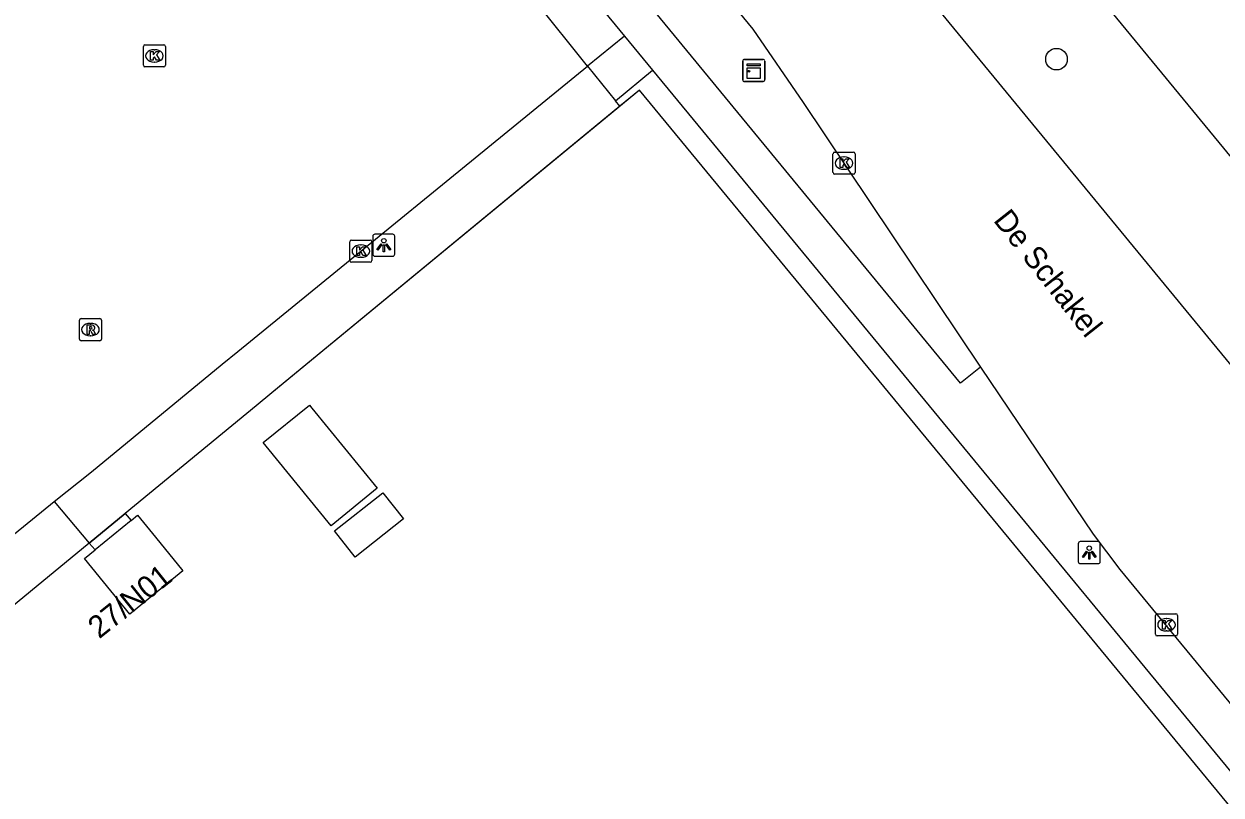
# Model space of a CAD drawing. Extents: x 156141 to 158132, y 385651 to 388399.
# Drawn here: x 157222.2 to 157276.3, y 386292.7 to 386327.6 of the extents above; entities that cross this region are included whole.
import ezdxf

# ---------------------------------------------------------------- set-up
doc = ezdxf.new("R2010")
doc.units = 0
for name, color, linetype in [('IMGEO_Boom', 7, 'Continuous'), ('IMGEO_Groenvoorziening', 7, 'Continuous'), ('IMGEO_Haag', 7, 'Continuous'), ('IMGEO_Hek', 7, 'Continuous'), ('IMGEO_Kast', 7, 'Continuous'), ('IMGEO_Kolk', 7, 'Continuous'), ('IMGEO_Lichtpunt', 7, 'Continuous'), ('IMGEO_Openbare_ruimte_label', 7, 'Continuous'), ('IMGEO_Pand', 7, 'Continuous'), ('IMGEO_Pand_nummerreeks', 7, 'Continuous'), ('IMGEO_Rijbaan_lokaal_gesloten', 7, 'Continuous'), ('IMGEO_Rioolput', 7, 'Continuous'), ('IMGEO_Voetpad_open', 7, 'Continuous')]:
    doc.layers.add(name, color=color, linetype=linetype)

msp = doc.modelspace()

# ---------------------------------------------------------------- linework, layer by layer
at = {"layer": 'IMGEO_Boom'}
msp.add_circle((157268.887, 386325.993), 0.489, dxfattribs=at)
at = {"layer": 'IMGEO_Groenvoorziening'}
for points in [[(157247.676, 386325.673), (157242.926, 386331.607), (157204.09, 386378.741)], [(157318.008, 386237.675), (157310.24, 386250.894), (157308.881, 386253.009), (157305.737, 386257.034), (157297.068, 386267.539), (157250.016, 386324.597), (157249.125, 386323.863)]]:
    msp.add_lwpolyline(points, dxfattribs=at)
at = {"layer": 'IMGEO_Haag'}
msp.add_lwpolyline([(157225.13, 386304.108), (157163.286, 386253.19), (157161.441, 386255.415), (157161.905, 386255.778), (157223.541, 386305.983)], dxfattribs=at)
at = {"layer": 'IMGEO_Hek'}
for points in [[(157297.068, 386267.539), (157250.016, 386324.597), (157233.385, 386310.904)], [(157233.385, 386310.904), (157232.673, 386310.318)], [(157232.673, 386310.318), (157226.757, 386305.447)], [(157226.757, 386305.447), (157225.13, 386304.108)], [(157225.13, 386304.108), (157163.286, 386253.19)]]:
    msp.add_lwpolyline(points, dxfattribs=at)
at = {"layer": 'IMGEO_Kast'}
for p, q in [((157254.691, 386325.06), (157254.691, 386325.901)), ((157254.691, 386325.901), (157254.691, 386325.06)), ((157254.766, 386325.985), (157255.607, 386325.985)), ((157255.607, 386325.985), (157254.766, 386325.985)), ((157255.691, 386325.91), (157255.691, 386325.069)), ((157255.691, 386325.069), (157255.691, 386325.91)), ((157255.616, 386324.985), (157254.775, 386324.985)), ((157254.775, 386324.985), (157255.616, 386324.985))]:
    msp.add_line(p, q, dxfattribs=at)
for points in [[(157254.886, 386325.775), (157255.486, 386325.775), (157255.486, 386325.69), (157254.886, 386325.69), (157254.886, 386325.775)], [(157254.886, 386325.6), (157255.486, 386325.6), (157255.486, 386325.111), (157254.886, 386325.111), (157254.886, 386325.6)]]:
    msp.add_lwpolyline(points, dxfattribs=at)
msp.add_circle((157254.97, 386325.449), 0.0377, dxfattribs=at)
for centre, start, end in [((157254.769, 386325.907), 92.4484, 184.2845), ((157254.769, 386325.907), 92.4484, 184.2845), ((157255.613, 386325.907), 2.4484, 94.2845), ((157255.613, 386325.907), 2.4484, 94.2845), ((157254.769, 386325.063), 182.4484, 274.2845), ((157254.769, 386325.063), 182.4484, 274.2845), ((157255.613, 386325.063), 272.4484, 4.2845), ((157255.613, 386325.063), 272.4484, 4.2845)]:
    msp.add_arc(centre, 0.0779, start, end, dxfattribs=at)
at = {"layer": 'IMGEO_Kolk'}
for p, q in [((157227.574, 386325.716), (157227.574, 386326.568)), ((157227.649, 386326.642), (157228.501, 386326.642)), ((157228.575, 386326.568), (157228.575, 386325.716)), ((157228.062, 386326.422), (157228.087, 386326.422)), ((157228.501, 386325.642), (157227.649, 386325.642)), ((157228.085, 386325.862), (157228.06, 386325.862)), ((157258.775, 386320.865), (157258.775, 386321.717)), ((157258.85, 386321.791), (157259.702, 386321.791)), ((157259.263, 386321.571), (157259.288, 386321.571)), ((157259.776, 386321.717), (157259.776, 386320.865)), ((157259.286, 386321.011), (157259.261, 386321.011)), ((157259.702, 386320.791), (157258.85, 386320.791)), ((157236.99, 386317.81), (157237.842, 386317.81)), ((157236.915, 386316.884), (157236.915, 386317.736)), ((157237.403, 386317.59), (157237.428, 386317.59)), ((157237.916, 386317.736), (157237.916, 386316.884)), ((157237.842, 386316.81), (157236.99, 386316.81)), ((157237.426, 386317.03), (157237.401, 386317.03)), ((157273.365, 386299.983), (157273.365, 386300.835)), ((157273.44, 386300.909), (157274.292, 386300.909)), ((157273.853, 386300.689), (157273.878, 386300.689)), ((157274.366, 386300.835), (157274.366, 386299.983)), ((157274.292, 386299.909), (157273.44, 386299.909)), ((157273.876, 386300.129), (157273.851, 386300.129))]:
    msp.add_line(p, q, dxfattribs=at)
for points in [[(157227.574, 386325.716), (157227.574, 386326.568)], [(157227.649, 386326.642), (157228.501, 386326.642)], [(157228.575, 386326.568), (157228.575, 386325.716)], [(157227.895, 386326.342), (157228.018, 386326.342), (157228.018, 386326.191), (157228.148, 386326.342), (157228.312, 386326.342), (157228.166, 386326.191), (157228.319, 386325.942), (157228.167, 386325.942), (157228.082, 386326.106), (157228.018, 386326.039), (157228.018, 386325.942), (157227.895, 386325.942), (157227.895, 386326.342)], [(157228.501, 386325.642), (157227.649, 386325.642)], [(157258.775, 386320.865), (157258.775, 386321.717)], [(157258.85, 386321.791), (157259.702, 386321.791)], [(157259.776, 386321.717), (157259.776, 386320.865)], [(157259.096, 386321.491), (157259.219, 386321.491), (157259.219, 386321.34), (157259.349, 386321.491), (157259.513, 386321.491), (157259.367, 386321.34), (157259.52, 386321.091), (157259.368, 386321.091), (157259.283, 386321.255), (157259.219, 386321.188), (157259.219, 386321.091), (157259.096, 386321.091), (157259.096, 386321.491)], [(157259.702, 386320.791), (157258.85, 386320.791)], [(157236.99, 386317.81), (157237.842, 386317.81)], [(157236.915, 386316.884), (157236.915, 386317.736)], [(157237.236, 386317.51), (157237.359, 386317.51), (157237.359, 386317.359), (157237.489, 386317.51), (157237.653, 386317.51), (157237.507, 386317.359), (157237.66, 386317.11), (157237.508, 386317.11), (157237.423, 386317.274), (157237.359, 386317.207), (157237.359, 386317.11), (157237.236, 386317.11), (157237.236, 386317.51)], [(157237.916, 386317.736), (157237.916, 386316.884)], [(157237.842, 386316.81), (157236.99, 386316.81)], [(157273.365, 386299.983), (157273.365, 386300.835)], [(157273.44, 386300.909), (157274.292, 386300.909)], [(157273.686, 386300.609), (157273.809, 386300.609), (157273.809, 386300.458), (157273.939, 386300.609), (157274.103, 386300.609), (157273.957, 386300.458), (157274.11, 386300.209), (157273.958, 386300.209), (157273.873, 386300.373), (157273.809, 386300.306), (157273.809, 386300.209), (157273.686, 386300.209), (157273.686, 386300.609)], [(157274.366, 386300.835), (157274.366, 386299.983)], [(157274.292, 386299.909), (157273.44, 386299.909)]]:
    msp.add_lwpolyline(points, dxfattribs=at)
for centre, start, end in [((157227.651, 386326.566), 91.552, 178.448), ((157227.651, 386326.566), 91.552, 178.448), ((157228.499, 386326.566), 1.552, 88.448), ((157228.499, 386326.566), 1.552, 88.448), ((157227.651, 386325.718), 181.552, 268.448), ((157227.651, 386325.718), 181.552, 268.448), ((157228.499, 386325.718), 271.552, 358.448), ((157228.499, 386325.718), 271.552, 358.448), ((157258.852, 386321.715), 91.552, 178.448), ((157258.852, 386321.715), 91.552, 178.448), ((157259.7, 386321.715), 1.552, 88.448), ((157259.7, 386321.715), 1.552, 88.448), ((157258.852, 386320.867), 181.552, 268.448), ((157258.852, 386320.867), 181.552, 268.448), ((157259.7, 386320.867), 271.552, 358.448), ((157259.7, 386320.867), 271.552, 358.448), ((157236.992, 386317.734), 91.552, 178.448), ((157236.992, 386317.734), 91.552, 178.448), ((157237.84, 386317.734), 1.552, 88.448), ((157237.84, 386317.734), 1.552, 88.448), ((157236.992, 386316.886), 181.552, 268.448), ((157236.992, 386316.886), 181.552, 268.448), ((157237.84, 386316.886), 271.552, 358.448), ((157237.84, 386316.886), 271.552, 358.448), ((157273.442, 386300.833), 91.552, 178.448), ((157273.442, 386300.833), 91.552, 178.448), ((157274.29, 386300.833), 1.552, 88.448), ((157274.29, 386300.833), 1.552, 88.448), ((157273.442, 386299.985), 181.552, 268.448), ((157273.442, 386299.985), 181.552, 268.448), ((157274.29, 386299.985), 271.552, 358.448), ((157274.29, 386299.985), 271.552, 358.448)]:
    msp.add_arc(centre, 0.0765, start, end, dxfattribs=at)
for centre, major_axis, ratio, start_param, end_param in [((157228.061, 386326.142), (-0.387, 0.002), 0.722429, 4.712389, 7.853982), ((157228.086, 386326.142), (-0.39, 0.002), 0.717154, 1.570796, 4.712389), ((157259.262, 386321.291), (-0.387, 0.002), 0.722429, 4.712389, 7.853982), ((157259.287, 386321.291), (-0.39, 0.002), 0.717154, 1.570796, 4.712389), ((157237.402, 386317.31), (-0.387, 0.002), 0.722429, 4.712389, 7.853982), ((157237.427, 386317.31), (-0.39, 0.002), 0.717154, 1.570796, 4.712389), ((157273.852, 386300.409), (-0.387, 0.002), 0.722429, 4.712389, 7.853982), ((157273.877, 386300.409), (-0.39, 0.002), 0.717154, 1.570796, 4.712389)]:
    msp.add_ellipse(centre, major_axis=major_axis, ratio=ratio, start_param=start_param, end_param=end_param, dxfattribs=at)
at = {"layer": 'IMGEO_Lichtpunt'}
for p, q in [((157237.955, 386317.981), (157237.955, 386317.174)), ((157237.955, 386317.981), (157237.955, 386317.174)), ((157238.857, 386318.076), (157238.049, 386318.076)), ((157238.857, 386318.076), (157238.049, 386318.076)), ((157238.951, 386317.174), (157238.951, 386317.981)), ((157238.951, 386317.174), (157238.951, 386317.981)), ((157238.049, 386317.08), (157238.857, 386317.08)), ((157238.049, 386317.08), (157238.857, 386317.08)), ((157269.87, 386304.076), (157269.87, 386303.269)), ((157269.87, 386304.076), (157269.87, 386303.269)), ((157270.772, 386304.171), (157269.964, 386304.171)), ((157270.772, 386304.171), (157269.964, 386304.171)), ((157270.866, 386303.269), (157270.866, 386304.076)), ((157270.866, 386303.269), (157270.866, 386304.076)), ((157269.964, 386303.175), (157270.772, 386303.175)), ((157269.964, 386303.175), (157270.772, 386303.175))]:
    msp.add_line(p, q, dxfattribs=at)
for points in [[(157238.329, 386317.645), (157238.368, 386317.617), (157238.18, 386317.355), (157238.142, 386317.382), (157238.329, 386317.645)], [(157238.431, 386317.597), (157238.478, 386317.597), (157238.478, 386317.275), (157238.431, 386317.275), (157238.431, 386317.597)], [(157238.541, 386317.617), (157238.579, 386317.644), (157238.766, 386317.382), (157238.727, 386317.354), (157238.541, 386317.617)], [(157270.244, 386303.74), (157270.283, 386303.712), (157270.095, 386303.45), (157270.057, 386303.477), (157270.244, 386303.74)], [(157270.346, 386303.692), (157270.393, 386303.692), (157270.393, 386303.37), (157270.346, 386303.37), (157270.346, 386303.692)], [(157270.456, 386303.712), (157270.494, 386303.739), (157270.681, 386303.477), (157270.642, 386303.449), (157270.456, 386303.712)]]:
    msp.add_lwpolyline(points, dxfattribs=at)
for centre in [(157238.454, 386317.779), (157270.369, 386303.874)]:
    msp.add_circle(centre, 0.0994, dxfattribs=at)
for centre, start, end in [((157238.049, 386317.981), 90, 180), ((157238.049, 386317.981), 90, 180), ((157238.857, 386317.981), 0, 90), ((157238.857, 386317.981), 0, 90), ((157238.049, 386317.174), 180, 270), ((157238.049, 386317.174), 180, 270), ((157238.857, 386317.174), 270, 0), ((157238.857, 386317.174), 270, 360), ((157269.964, 386304.076), 90, 180), ((157269.964, 386304.076), 90, 180), ((157270.772, 386304.076), 0, 90), ((157270.772, 386304.076), 0, 90), ((157269.964, 386303.269), 180, 270), ((157269.964, 386303.269), 180, 270), ((157270.772, 386303.269), 270, 0), ((157270.772, 386303.269), 270, 360)]:
    msp.add_arc(centre, 0.0946, start, end, dxfattribs=at)
at = {"layer": 'IMGEO_Pand'}
for points in [[(157233.128, 386308.491), (157232.999, 386308.65), (157235.084, 386310.349), (157235.204, 386310.201), (157238.154, 386306.582), (157236.069, 386304.883), (157233.128, 386308.491)], [(157238.407, 386306.377), (157239.339, 386305.198), (157237.159, 386303.475), (157236.227, 386304.654), (157238.407, 386306.377)], [(157227.019, 386305.124), (157227.309, 386305.361), (157228.122, 386304.37), (157229.365, 386302.857), (157226.965, 386300.89), (157224.909, 386303.4), (157225.394, 386303.796)], [(157227.019, 386305.124), (157225.394, 386303.796)]]:
    msp.add_lwpolyline(points, dxfattribs=at)
at = {"layer": 'IMGEO_Rijbaan_lokaal_gesloten'}
for points in [[(157203.781, 386410.196), (157205.755, 386407.826), (157335.682, 386250), (157341.401, 386242.711), (157342.288, 386241.546)], [(157337.285, 386238.671), (157336.115, 386240.102), (157327.942, 386250), (157201.153, 386404.033), (157199.193, 386406.39)], [(157194.1, 386401.515), (157255.15, 386327.344), (157257.428, 386324.032), (157265.451, 386312.065)], [(157265.451, 386312.065), (157270.545, 386304.503), (157271.759, 386302.908), (157316.481, 386248.624)]]:
    msp.add_lwpolyline(points, dxfattribs=at)
at = {"layer": 'IMGEO_Rioolput'}
for p, q in [((157224.68, 386313.334), (157224.68, 386314.186)), ((157224.755, 386314.26), (157225.607, 386314.26)), ((157225.168, 386314.04), (157225.193, 386314.04)), ((157225.681, 386314.186), (157225.681, 386313.334)), ((157225.191, 386313.48), (157225.166, 386313.48)), ((157225.607, 386313.26), (157224.755, 386313.26))]:
    msp.add_line(p, q, dxfattribs=at)
for points in [[(157224.68, 386313.334), (157224.68, 386314.186)], [(157224.755, 386314.26), (157225.607, 386314.26)], [(157225.681, 386314.186), (157225.681, 386313.334)], [(157225.269, 386313.958), (157225.017, 386313.96), (157225.017, 386313.56)], [(157225.017, 386313.56), (157225.141, 386313.56), (157225.141, 386313.722), (157225.152, 386313.722)], [(157225.195, 386313.879), (157225.141, 386313.879), (157225.141, 386313.798)], [(157225.141, 386313.798), (157225.193, 386313.798)], [(157225.199, 386313.693), (157225.27, 386313.56), (157225.41, 386313.56), (157225.345, 386313.686)], [(157225.607, 386313.26), (157224.755, 386313.26)]]:
    msp.add_lwpolyline(points, dxfattribs=at)
for centre, radius, start, end in [((157224.757, 386314.184), 0.0765, 91.552, 178.448), ((157224.757, 386314.184), 0.0765, 91.552, 178.448), ((157225.605, 386314.184), 0.0765, 1.552, 88.448), ((157225.605, 386314.184), 0.0765, 1.552, 88.448), ((157225.151, 386313.669), 0.0533, 26.0293, 88.6989), ((157225.177, 386313.987), 0.19, 274.7715, 282.9687), ((157225.201, 386313.783), 0.0964, 77.0061, 93.1865), ((157225.215, 386313.84), 0.0378, 276.6634, 79.6772), ((157225.268, 386313.848), 0.109, 350.3612, 89.416), ((157225.266, 386313.848), 0.112, 277.5842, 350.9817), ((157225.25, 386313.633), 0.108, 29.5134, 73.7905), ((157224.757, 386313.336), 0.0765, 181.552, 268.448), ((157224.757, 386313.336), 0.0765, 181.552, 268.448), ((157225.605, 386313.336), 0.0765, 271.552, 358.448), ((157225.605, 386313.336), 0.0765, 271.552, 358.448)]:
    msp.add_arc(centre, radius, start, end, dxfattribs=at)
for centre, major_axis, ratio, start_param, end_param in [((157225.167, 386313.76), (-0.387, 0.002), 0.722429, 4.712389, 7.853982), ((157225.192, 386313.76), (-0.39, 0.002), 0.717154, 1.570796, 4.712389)]:
    msp.add_ellipse(centre, major_axis=major_axis, ratio=ratio, start_param=start_param, end_param=end_param, dxfattribs=at)
at = {"layer": 'IMGEO_Voetpad_open'}
for points in [[(157265.451, 386312.065), (157264.546, 386311.336), (157211.154, 386376.22)], [(157209.826, 386374.969), (157249.344, 386327.032)], [(157249.344, 386327.032), (157247.676, 386325.673)], [(157249.344, 386327.032), (157250.614, 386325.491)], [(157223.541, 386305.983), (157225.229, 386307.333), (157231.137, 386312.191), (157231.851, 386312.773), (157247.676, 386325.673)], [(157247.676, 386325.673), (157248.932, 386324.105)], [(157248.932, 386324.105), (157250.614, 386325.491)], [(157250.614, 386325.491), (157310.849, 386252.423), (157319.091, 386238.264)], [(157249.125, 386323.863), (157233.385, 386310.904), (157232.673, 386310.318), (157226.757, 386305.447)], [(157249.125, 386323.863), (157248.932, 386324.105)], [(157223.541, 386305.983), (157225.13, 386304.108)], [(157225.13, 386304.108), (157226.757, 386305.447)], [(157226.757, 386305.447), (157227.019, 386305.124)], [(157225.394, 386303.796), (157225.13, 386304.108)]]:
    msp.add_lwpolyline(points, dxfattribs=at)

# ---------------------------------------------------------------- texts
at = {"layer": 'IMGEO_Openbare_ruimte_label'}
msp.add_text('De Schakel', height=1, rotation=308.302, dxfattribs=at).set_placement((157265.998, 386318.695))
at = {"layer": 'IMGEO_Pand_nummerreeks'}
msp.add_text('27/N01', height=1, rotation=38.5546, dxfattribs=at).set_placement((157225.576, 386299.747))

doc.saveas('drawing.dxf')
